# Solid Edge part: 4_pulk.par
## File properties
Author: Romil
Template: iso part.par
Last saved by: Romil
Revision: 30
Application: Solid Edge
Accuracy: 0.990
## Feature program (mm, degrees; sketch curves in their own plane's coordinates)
sketch for "unnamed Protrusion 1" plane through (0, 0, 0) normal (1, 0, 0) x-axis (0, 1, 0)
  arc centre (0, 0) radius 2.35 from (2.181, 0.875) to (2.181, -0.875) cw
  arc centre (0, 0) radius 2.35 from (-0.875, 2.181) to (0.875, 2.181) cw
  arc centre (0, 0) radius 2.35 from (-2.181, -0.875) to (-2.181, 0.875) cw
extrude "unnamed Protrusion 1" add finite 31.2 symmetric
fillet "Round_4" radius 0.55  Radii2 = 0.2 mm
mirror "unnamed Mirror 1" of "Round_4" about plane through (0, 0, 0) normal (1, 0, 0)
fillet "unnamed Round 1"
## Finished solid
Body 1: solid body, 50 faces, 128 edges, 80 vertices.
  Faces by surface: cylinder 24, torus 16, plane 10
  Edges by curve: circle 48, line 48, intersection 32
Bounding box of the edges (mm; curved faces can reach further): 31.200 x 4.700 x 4.700, from (-15.6, -2.35, -2.35) to (15.6, 2.35, 2.35).
Cylindrical faces by radius (mm): R0.1 x4, R0.2 x16, R2.35 x4
Toroidal faces (ring radius, tube radius in mm): R0.3 r0.2 x8, R1.8 r0.55 x8
Planar faces by outward normal: +x 1, +y 2, +z 2, -x 1, -y 2, -z 2
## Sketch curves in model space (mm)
arc centre (0, -0.975, -0.975) radius 0.1 from (0, -0.975, -0.875) through (0, -0.9023, -0.9064) to (0, -0.875, -0.975)
line (0, -0.875, -0.975) -> (0, -0.875, -2.181)
arc centre (0, 0, 0) radius 2.35 from (0, 0.875, -2.181) through (0, 0, -2.35) to (0, -0.875, -2.181)
line (0, 0.875, -2.181) -> (0, 0.875, -0.975)
arc centre (0, 0.975, -0.975) radius 0.1 from (0, 0.875, -0.975) through (0, 0.9064, -0.9023) to (0, 0.975, -0.875)
line (0, 0.975, -0.875) -> (0, 2.181, -0.875)
arc centre (0, 0, 0) radius 2.35 from (0, 2.181, 0.875) through (0, 2.35, 0) to (0, 2.181, -0.875)
line (0, 2.181, 0.875) -> (0, 0.975, 0.875)
arc centre (0, 0.975, 0.975) radius 0.1 from (0, 0.975, 0.875) through (0, 0.9023, 0.9064) to (0, 0.875, 0.975)
line (0, 0.875, 0.975) -> (0, 0.875, 2.181)
arc centre (0, 0, 0) radius 2.35 from (0, -0.875, 2.181) through (0, 0, 2.35) to (0, 0.875, 2.181)
line (0, -0.875, 2.181) -> (0, -0.875, 0.975)
arc centre (0, -0.975, 0.975) radius 0.1 from (0, -0.875, 0.975) through (0, -0.9064, 0.9023) to (0, -0.975, 0.875)
line (0, -0.975, 0.875) -> (0, -2.181, 0.875)
arc centre (0, 0, 0) radius 2.35 from (0, -2.181, -0.875) through (0, -2.35, 0) to (0, -2.181, 0.875)
line (0, -2.181, -0.875) -> (0, -0.975, -0.875)
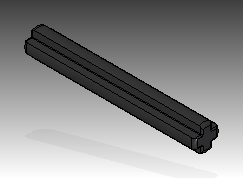
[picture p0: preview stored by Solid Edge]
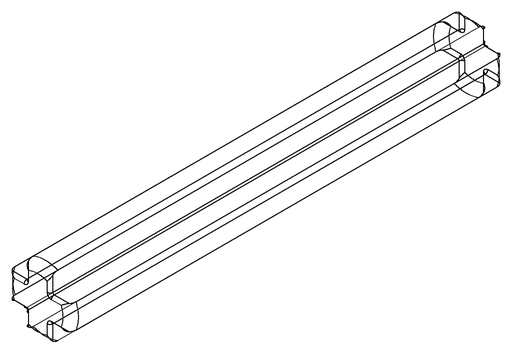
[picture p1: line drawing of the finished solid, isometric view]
